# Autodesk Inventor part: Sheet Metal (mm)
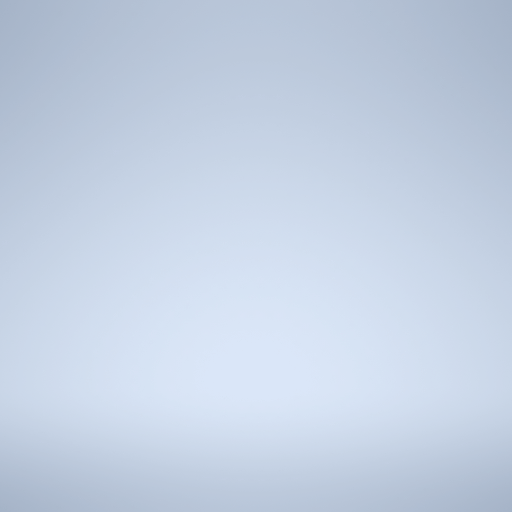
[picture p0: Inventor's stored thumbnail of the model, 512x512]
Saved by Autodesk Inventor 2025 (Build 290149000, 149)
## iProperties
Created: 2024-02
Part Number: Sheet Metal (mm)
Material: Generico
Document SubType Name: Sheet Metal
Density: 1 g/cm^3
Sheet Metal Rule: Default_mm
Appearance: Default
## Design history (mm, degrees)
other parameters: "Spessore" = 0.5, "RaggioPiega" = 0.5 (= Spessore), "LarghezzaScaricoPiega" = 0.5 (= Spessore), "ProfonditàScaricoPiega" = 0.25 (= 0.5 x Spessore), "DimensioniScaricoAngolo" = 2 (= 4 x Spessore), "SeamGap" = 0.01, "ResiduoMinimo" = 1 (= 2 x Spessore), "RaggioTransizione" = 0.5 (= RaggioPiega), "Dimensione_raggio_Jacobi" = 0.5 (= RaggioPiega), "DimensioneGioco" = 0.5 (= Spessore)
